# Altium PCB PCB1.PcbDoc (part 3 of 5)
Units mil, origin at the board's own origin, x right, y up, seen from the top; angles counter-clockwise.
Board outline 4463 x 4481 mil, 2 copper layers (Top Layer, Bottom Layer); 0 components, 111 nets, 310 pads, 0 vias.
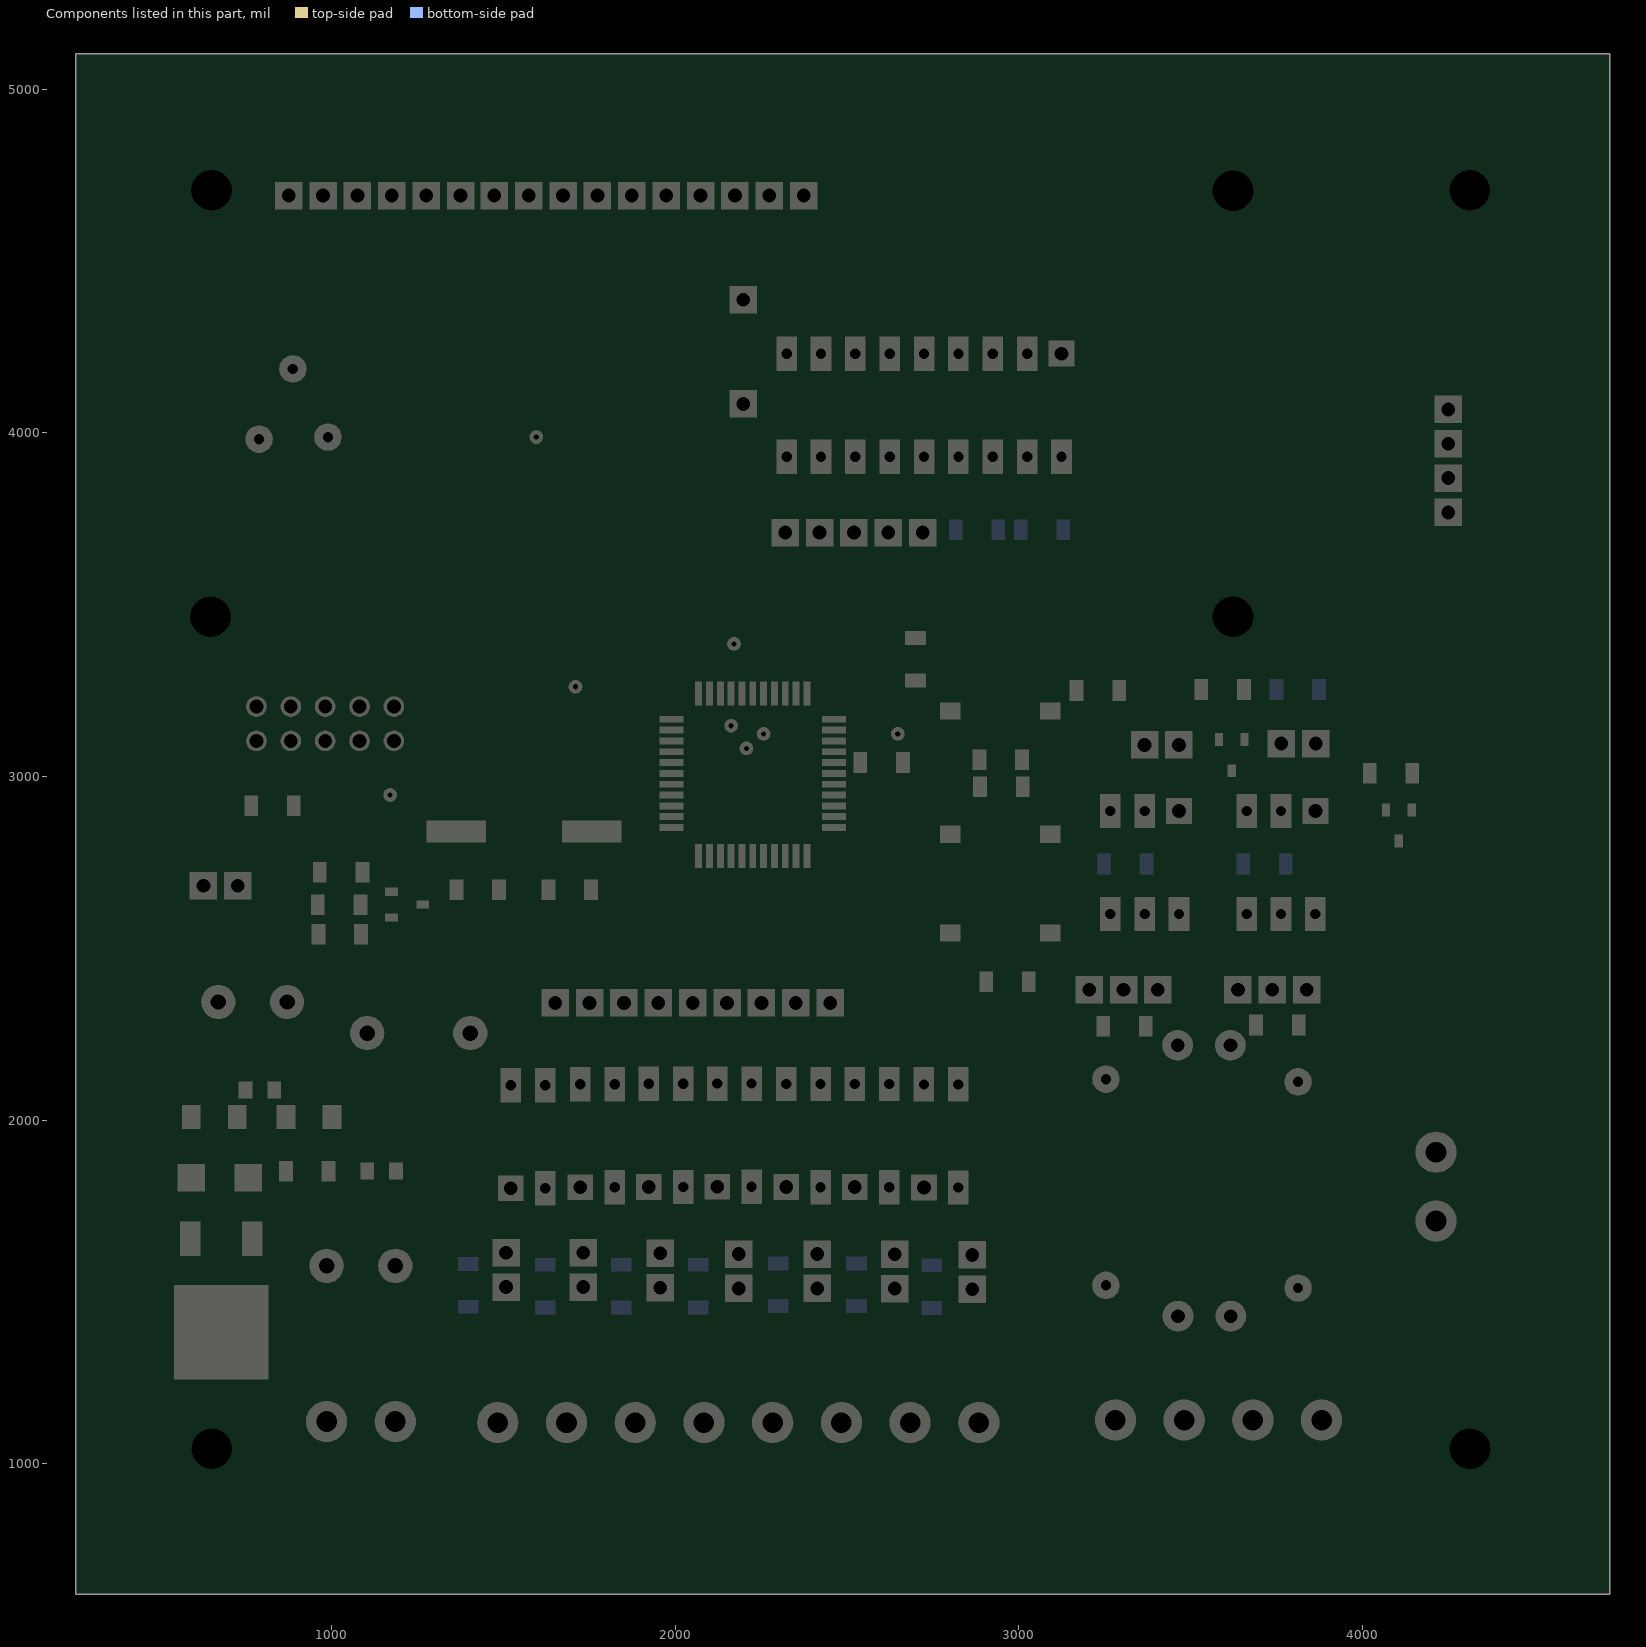
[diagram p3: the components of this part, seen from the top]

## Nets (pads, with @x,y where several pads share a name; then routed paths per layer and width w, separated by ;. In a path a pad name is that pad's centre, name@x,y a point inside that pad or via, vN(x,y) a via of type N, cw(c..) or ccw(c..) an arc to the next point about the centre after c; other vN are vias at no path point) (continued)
copper on no net: (continued)
  Top Layer w15: 3289.04,2179.3 3289.04,2215.2 ; 3289.04,2446.5 3289.04,2522 ; 3289.04,2677 3289.04,2822 ; 3289.04,2976.9 3289.04,3072 ; 3289.04,3694.8 3289.04,4351.8 ; 3289.04,4421.8 3289.04,4841.9 ; 3293.34,2231.9 3322.34,2231.9 ; 3293.34,2256.9 3322.34,2256.9 ; 3293.34,2281.9 3322.34,2281.9 ; 3293.34,2306.9 3322.34,2306.9 ; 3311.44,1556.9 3762.94,1556.9 ; 3311.44,2156.9 3420.54,2156.9 ; 3311.94,1481.9 3413.54,1481.9 ; 3311.94,2081.9 3746.74,2081.9 ; 3314.04,906.9 3314.04,1039.5 ; 3314.04,1214.5 3314.04,1484 ; 3314.04,1554.3 3314.04,2084 ; 3314.04,2154.3 3314.04,2311.5 ; 3314.04,2446.5 3314.04,2522 ; 3314.04,2677 3314.04,2822 ; 3314.04,2976.9 3314.04,3024 ; 3314.04,3719.8 3314.04,4351.8 ; 3314.04,4421.8 3314.04,4841.9 ; 3321.24,1506.9 3745.34,1506.9 ; 3321.24,1531.9 3745.34,1531.9 ; 3321.24,2106.9 3745.34,2106.9 ; 3321.24,2131.9 3745.34,2131.9 ; 3325.14,1206.9 3437.44,1206.9 ; 3334.94,1056.9 3427.64,1056.9 ; 3339.04,906.9 3339.04,1061 ; 3339.04,1193.1 3339.04,2215.2 ; 3339.04,2446.5 3339.04,2522 ; 3339.04,2677 3339.04,2822 ; 3339.04,2999.5 3339.04,3024 ; 3339.04,3744.8 3339.04,4351.8 ; 3339.04,4421.8 3339.04,4841.9 ; 3350.14,1181.9 3412.44,1181.9 ; 3359.94,1081.9 3402.64,1081.9 ; 3364.04,906.9 3364.04,1086 ; 3364.04,1168.1 3364.04,2215.2 ; 3364.04,2446.5 3364.04,2522 ; 3364.04,2677 3364.04,2822 ; 3364.04,3769.8 3364.04,4351.8 ; 3364.04,4421.8 3364.04,4841.9 ; 3368.84,1106.9 3393.84,1106.9 ; 3368.84,1131.9 3393.84,1131.9 ; 3368.84,1156.9 3393.84,1156.9 ; 3389.04,906.9 3389.04,2215.2 ; 3389.04,2446.5 3389.04,2522 ; 3389.04,2677 3389.04,2822 ; 3389.04,3794.8 3389.04,4351.8 ; 3389.04,4421.8 3389.04,4841.9 ; 3414.04,906.9 3414.04,1070.6 ; 3414.04,1183.5 3414.04,1376.6 ; 3414.04,1482.4 3414.04,2163.4 ; 3414.04,2446.5 3414.04,2522 ; 3414.04,2677 3414.04,2822 ; 3414.04,3802.9 3414.04,4351.8 ; 3414.04,4421.8 3414.04,4841.9 ; 3423.84,2831.9 3605.74,2831.9 ; 3439.04,906.9 3439.04,1045.6 ; 3439.04,1208.5 3439.04,1357 ; 3439.04,1502 3439.04,2145.1 ; 3439.04,2290.1 3439.04,2292.4 ; 3439.04,2446.5 3439.04,2522 ; 3439.04,2677 3439.04,2834.5 ; 3439.04,2964.4 3439.04,2981.7 ; 3439.04,3802.9 3439.04,4351.8 ; 3439.04,4421.8 3439.04,4841.9 ; 3440.34,2306.9 3611.04,2306.9 ; 3464.04,906.9 3464.04,1039.5 ; 3464.04,1214.5 3464.04,1357 ; 3464.04,1502 3464.04,2145.1 ; 3464.04,2290.1 3464.04,2311.5 ; 3464.04,2446.5 3464.04,2522 ; 3464.04,2677 3464.04,2834.5 ; 3464.04,2964.4 3464.04,2981.7 ; 3464.04,3802.9 3464.04,4351.8 ; 3464.04,4421.8 3464.04,4841.9 ; 3472.44,2331.9 3570.54,2331.9 ; 3472.44,2356.9 3570.54,2356.9 ; 3472.44,2381.9 3570.54,2381.9 ; 3472.44,2406.9 3570.54,2406.9 ; 3472.44,2431.9 3570.54,2431.9 ; 3489.04,906.9 3489.04,1039.5 ; 3489.04,1214.5 3489.04,1357 ; 3489.04,1502 3489.04,2145.1 ; 3489.04,2290.1 3489.04,2522 ; 3489.04,2677 3489.04,2834.5 ; 3489.04,2964.4 3489.04,2981.7 ; 3489.04,3802.9 3489.04,4351.8 ; 3489.04,4421.8 3489.04,4841.9 ; 3500.64,2281.9 3577.74,2281.9 ; 3504.24,2156.9 3574.04,2156.9 ; 3513.74,1481.9 3567.04,1481.9 ; 3514.04,906.9 3514.04,1039.5 ; 3514.04,1214.5 3514.04,1377.4 ; 3514.04,1481.6 3514.04,2166.7 ; 3514.04,2268.5 3514.04,2522 ; 3514.04,2677 3514.04,2834.5 ; 3514.04,2964.4 3514.04,2981.7 ; 3514.04,3802.9 3514.04,4351.8 ; 3514.04,4421.8 3514.04,4841.9 ; 3518.54,1381.9 3562.14,1381.9 ; 3523.84,2531.9 3605.74,2531.9 ; 3523.84,2556.9 3605.74,2556.9 ; 3523.84,2581.9 3605.74,2581.9 ; 3523.84,2606.9 3605.74,2606.9 ; 3523.84,2631.9 3605.74,2631.9 ; 3523.84,2656.9 3605.74,2656.9 ; 3525.14,1206.9 3637.44,1206.9 ; 3525.64,2256.9 3552.74,2256.9 ; 3529.24,2181.9 3549.04,2181.9 ; 3531.34,2856.9 3605.74,2856.9 ; 3531.34,2881.9 3605.74,2881.9 ; 3531.34,2906.9 3605.74,2906.9 ; 3531.34,2931.9 3605.74,2931.9 ; 3531.34,2956.9 3605.74,2956.9 ; 3534.94,1056.9 3627.64,1056.9 ; 3534.94,2206.9 3543.44,2206.9 ; 3534.94,2231.9 3543.44,2231.9 ; 3536.14,1406.9 3544.64,1406.9 ; 3536.14,1431.9 3544.64,1431.9 ; 3536.14,1456.9 3544.64,1456.9 ; 3539.04,906.9 3539.04,1061 ; 3539.04,1193.1 3539.04,2981.7 ; 3539.04,3802.9 3539.04,4351.8 ; 3539.04,4421.8 3539.04,4666 ; 3539.04,4742.1 3539.04,4841.9 ; 3550.14,1181.9 3612.44,1181.9 ; 3559.94,1081.9 3602.64,1081.9 ; 3564.04,906.9 3564.04,1086 ; 3564.04,1168.1 3564.04,1380.1 ; 3564.04,1478.9 3564.04,2167 ; 3564.04,2268.2 3564.04,2981.7 ; 3564.04,3802.9 3564.04,4351.8 ; 3564.04,4421.8 3564.04,4641 ; 3564.04,4767.1 3564.04,4841.9 ; 3568.84,1106.9 3593.84,1106.9 ; 3568.84,1131.9 3593.84,1131.9 ; 3568.84,1156.9 3593.84,1156.9 ; 3589.04,906.9 3589.04,1357 ; 3589.04,1502 3589.04,2145.1 ; 3589.04,2290.1 3589.04,2311.5 ; 3589.04,2446.5 3589.04,2970.7 ; 3589.04,3802.9 3589.04,4351.8 ; 3589.04,4421.8 3589.04,4617.5 ; 3589.04,4790.6 3589.04,4841.9 ; 3614.04,906.9 3614.04,1070.6 ; 3614.04,1183.5 3614.04,1357 ; 3614.04,1502 3614.04,2145.1 ; 3614.04,2290.1 3614.04,2303.9 ; 3614.04,2446.5 3614.04,2522 ; 3614.04,2677 3614.04,2822 ; 3614.04,3802.9 3614.04,4351.8 ; 3614.04,4421.8 3614.04,4617.5 ; 3614.04,4790.6 3614.04,4841.9 ; 3639.04,906.9 3639.04,1045.6 ; 3639.04,1208.5 3639.04,1357 ; 3639.04,1502 3639.04,2145.1 ; 3639.04,2446.5 3639.04,2522 ; 3639.04,2677 3639.04,2822 ; 3639.04,3802.9 3639.04,4351.8 ; 3639.04,4421.8 3639.04,4617.5 ; 3639.04,4790.6 3639.04,4841.9 ; 3657.74,2156.9 3762.94,2156.9 ; 3664.04,906.9 3664.04,1039.5 ; 3664.04,1214.5 3664.04,1373.8 ; 3664.04,1485.2 3664.04,2163.2 ; 3664.04,2446.5 3664.04,2522 ; 3664.04,2677 3664.04,2822 ; 3664.04,3802.9 3664.04,4344.3 ; 3664.04,4421.8 3664.04,4622.3 ; 3664.04,4785.8 3664.04,4841.9 ; 3667.24,1481.9 3746.74,1481.9 ; 3667.94,4781.9 4267.04,4781.9 ; 3672.14,1381.9 4450.24,1381.9 ; 3673.64,4631.9 4262.94,4631.9 ; 3682.74,2181.9 4450.24,2181.9 ; 3688.44,2206.9 4450.24,2206.9 ; 3689.04,906.9 3689.04,1039.5 ; 3689.04,1214.5 3689.04,1398.8 ; 3689.04,1460.2 3689.04,2219.1 ; 3689.04,2446.5 3689.04,2522 ; 3689.04,2677 3689.04,2822 ; 3689.04,3802.9 3689.04,4319.3 ; 3689.04,4418.3 3689.04,4647.3 ; 3689.04,4760.8 3689.04,4841.9 ; 3689.64,1406.9 4450.24,1406.9 ; 3689.64,1431.9 4450.24,1431.9 ; 3689.64,1456.9 3771.74,1456.9 ; 3692.94,4756.9 4242.04,4756.9 ; 3698.64,4656.9 4237.94,4656.9 ; 3700.44,4406.9 4450.24,4406.9 ; 3709.94,4681.9 4225.84,4681.9 ; 3709.94,4706.9 4225.84,4706.9 ; 3709.94,4731.9 4225.84,4731.9 ; 3714.04,906.9 3714.04,1039.5 ; 3714.04,1214.5 3714.04,2219.1 ; 3714.04,2446.5 3714.04,2522 ; 3714.04,2677 3714.04,2822 ; 3714.04,3802.9 3714.04,4294.3 ; 3714.04,4393.3 3714.04,4841.9 ; 3725.14,1206.9 3837.44,1206.9 ; 3725.44,4381.9 4450.24,4381.9 ; 3734.94,1056.9 3827.64,1056.9 ; 3738.24,2231.9 3767.24,2231.9 ; 3738.24,2256.9 3767.24,2256.9 ; 3738.24,2281.9 3767.24,2281.9 ; 3738.24,2306.9 3767.24,2306.9 ; 3739.04,906.9 3739.04,1061 ; 3739.04,1193.1 3739.04,2311.5 ; 3739.04,2446.5 3739.04,2522 ; 3739.04,2677 3739.04,2807.2 ; 3739.04,3802.9 3739.04,4269.3 ; 3739.04,4368.3 3739.04,4841.9 ; 3750.14,1181.9 3812.44,1181.9 ; 3750.44,4356.9 4450.24,4356.9 ; 3759.94,1081.9 3802.64,1081.9 ; 3764.04,906.9 3764.04,1086 ; 3764.04,1168.1 3764.04,1464.6 ; 3764.04,1558 3764.04,2064.6 ; 3764.04,2158 3764.04,2311.5 ; 3764.04,2446.5 3764.04,2522 ; 3764.04,2677 3764.04,2782.2 ; 3764.04,3802.9 3764.04,4244.3 ; 3764.04,4343.3 3764.04,4841.9 ; 3768.84,1106.9 3793.84,1106.9 ; 3768.84,1131.9 3793.84,1131.9 ; 3768.84,1156.9 3793.84,1156.9 ; 3775.44,4331.9 4450.24,4331.9 ; 3789.04,906.9 3789.04,1443.8 ; 3789.04,1578.8 3789.04,2043.8 ; 3789.04,2178.8 3789.04,2219.1 ; 3789.04,2446.5 3789.04,2522 ; 3789.04,2677 3789.04,2777.1 ; 3789.04,3802.9 3789.04,4219.3 ; 3789.04,4318.3 3789.04,4841.9 ; 3800.44,4306.9 4450.24,4306.9 ; 3814.04,906.9 3814.04,1070.6 ; 3814.04,1183.5 3814.04,1443.8 ; 3814.04,1578.8 3814.04,2043.8 ; 3814.04,2178.8 3814.04,2219.1 ; 3814.04,2446.5 3814.04,2522 ; 3814.04,2677 3814.04,2777.1 ; 3814.04,3802.9 3814.04,4194.3 ; 3814.04,4293.3 3814.04,4841.9 ; 3825.44,4281.9 4450.24,4281.9 ; 3839.04,906.9 3839.04,1045.6 ; 3839.04,1208.5 3839.04,1443.8 ; 3839.04,1578.8 3839.04,2043.8 ; 3839.04,2178.8 3839.04,2219.1 ; 3839.04,2446.5 3839.04,2522 ; 3839.04,2677 3839.04,2777.1 ; 3839.04,3802.9 3839.04,4169.3 ; 3839.04,4268.3 3839.04,4841.9 ; 3850.44,4256.9 4450.24,4256.9 ; 3853.84,1456.9 4450.24,1456.9 ; 3853.84,2056.9 4450.24,2056.9 ; 3862.24,2231.9 4450.24,2231.9 ; 3862.24,2256.9 4450.24,2256.9 ; 3862.64,1556.9 4450.24,1556.9 ; 3862.64,2156.9 4450.24,2156.9 ; 3864.04,906.9 3864.04,1039.5 ; 3864.04,1214.5 3864.04,1467.1 ; 3864.04,1555.5 3864.04,2067.1 ; 3864.04,2155.5 3864.04,2276.4 ; 3864.04,2446.5 3864.04,2522 ; 3864.04,2677 3864.04,2777.1 ; 3864.04,3802.9 3864.04,4144.3 ; 3864.04,4243.3 3864.04,4841.9 ; 3869.54,2281.9 4450.24,2281.9 ; 3873.04,2306.9 4450.24,2306.9 ; 3875.44,4231.9 4450.24,4231.9 ; 3878.84,1481.9 4450.24,1481.9 ; 3878.84,2081.9 4450.24,2081.9 ; 3880.34,1506.9 4450.24,1506.9 ; 3880.34,1531.9 4450.24,1531.9 ; 3880.34,2106.9 4450.24,2106.9 ; 3880.34,2131.9 4450.24,2131.9 ; 3889.04,906.9 3889.04,1039.5 ; 3889.04,1214.5 3889.04,2311.5 ; 3889.04,2446.5 3889.04,2522 ; 3889.04,2677 3889.04,2777.1 ; 3889.04,3802.9 3889.04,4119.3 ; 3889.04,4218.3 3889.04,4841.9 ; 3900.44,4206.9 4450.24,4206.9 ; 3905.54,2331.9 4450.24,2331.9 ; 3905.54,2356.9 4450.24,2356.9 ; 3905.54,2381.9 4450.24,2381.9 ; 3905.54,2406.9 4450.24,2406.9 ; 3905.54,2431.9 4450.24,2431.9 ; 3914.04,906.9 3914.04,1039.5 ; 3914.04,1214.5 3914.04,2522 ; 3914.04,2677 3914.04,2777.1 ; 3914.04,3802.9 3914.04,4094.3 ; 3914.04,4193.3 3914.04,4841.9 ; 3920.74,2531.9 4450.24,2531.9 ; 3920.74,2556.9 4450.24,2556.9 ; 3920.74,2581.9 4450.24,2581.9 ; 3920.74,2606.9 4450.24,2606.9 ; 3920.74,2631.9 4450.24,2631.9 ; 3920.74,2656.9 4450.24,2656.9 ; 3925.14,1206.9 4450.24,1206.9 ; 3925.44,4181.9 4450.24,4181.9 ; 3934.94,1056.9 4226.64,1056.9 ; 3939.04,906.9 3939.04,1061 ; 3939.04,1193.1 3939.04,2777.1 ; 3939.04,3802.9 3939.04,4069.3 ; 3939.04,4168.3 3939.04,4841.9 ; 3950.14,1181.9 4450.24,1181.9 ; 3950.44,4156.9 4450.24,4156.9 ; 3959.94,1081.9 4229.14,1081.9 ; 3964.04,906.9 3964.04,1086 ; 3964.04,1168.1 3964.04,2777.1 ; 3964.04,3802.9 3964.04,4044.3 ; 3964.04,4143.3 3964.04,4841.9 ; 3968.84,1106.9 4254.14,1106.9 ; 3968.84,1131.9 4450.24,1131.9 ; 3968.84,1156.9 4450.24,1156.9 ; 3975.44,4131.9 4182.34,4131.9 ; 3989.04,906.9 3989.04,2777.1 ; 3989.04,3802.9 3989.04,4019.3 ; 3989.04,4118.3 3989.04,4841.9 ; 4000.44,4106.9 4182.34,4106.9 ; 4014.04,906.9 4014.04,2777.1 ; 4014.04,3802.9 4014.04,3994.3 ; 4014.04,4093.3 4014.04,4841.9 ; 4025.44,4081.9 4182.34,4081.9 ; 4039.04,906.9 4039.04,2777.1 ; 4039.04,4068.3 4039.04,4841.9 ; 4050.44,4056.9 4182.34,4056.9 ; 4064.04,906.9 4064.04,2777.1 ; 4064.04,4043.3 4064.04,4841.9 ; 4075.44,4031.9 4182.34,4031.9 ; 4089.04,906.9 4089.04,2766.1 ; 4089.04,4018.3 4089.04,4841.9 ; 4100.44,4006.9 4182.34,4006.9 ; 4103.74,3081.9 4450.24,3081.9 ; 4103.74,3106.9 4450.24,3106.9 ; 4103.74,3131.9 4450.24,3131.9 ; 4103.74,3156.9 4450.24,3156.9 ; 4103.74,3181.9 4450.24,3181.9 ; 4103.74,3206.9 4450.24,3206.9 ; 4103.74,3231.9 4450.24,3231.9 ; 4103.74,3256.9 4450.24,3256.9 ; 4103.74,3281.9 4450.24,3281.9 ; 4103.74,3306.9 4450.24,3306.9 ; 4103.74,3331.9 4450.24,3331.9 ; 4103.74,3356.9 4450.24,3356.9 ; 4103.74,3381.9 4450.24,3381.9 ; 4103.74,3406.9 4450.24,3406.9 ; 4103.74,3431.9 4450.24,3431.9 ; 4103.74,3456.9 4450.24,3456.9 ; 4103.74,3481.9 4450.24,3481.9 ; 4103.74,3506.9 4450.24,3506.9 ; 4103.74,3531.9 4450.24,3531.9 ; 4103.74,3556.9 4450.24,3556.9 ; 4103.74,3581.9 4450.24,3581.9 ; 4103.74,3606.9 4450.24,3606.9 ; 4103.74,3631.9 4450.24,3631.9 ; 4103.74,3656.9 4450.24,3656.9 ; 4103.74,3681.9 4450.24,3681.9 ; 4103.74,3706.9 4182.34,3706.9 ; 4103.74,3731.9 4182.34,3731.9 ; 4103.74,3806.9 4182.34,3806.9 ; 4103.74,3831.9 4182.34,3831.9 ; 4103.74,3856.9 4182.34,3856.9 ; 4103.74,3881.9 4182.34,3881.9 ; 4103.74,3906.9 4182.34,3906.9 ; 4103.74,3931.9 4182.34,3931.9 ; 4103.74,3956.9 4182.34,3956.9 ; 4103.74,3981.9 4182.34,3981.9 ; 4114.04,906.9 4114.04,2766.1 ; 4114.04,3066.3 4114.04,3732.9 ; 4114.04,3802.9 4114.04,4841.9 ; 4139.04,906.9 4139.04,1658.1 ; 4139.04,1755 4139.04,1858.1 ; 4139.04,1955 4139.04,2766.1 ; 4139.04,3066.3 4139.04,3732.9 ; 4139.04,3802.9 4139.04,4841.9 ; 4145.64,2781.9 4450.24,2781.9 ; 4145.64,2806.9 4450.24,2806.9 ; 4145.64,2831.9 4450.24,2831.9 ; 4164.04,906.9 4164.04,1633.1 ; 4164.04,1780 4164.04,1833.1 ; 4164.04,1980 4164.04,2856.6 ; 4164.04,3066.3 4164.04,3732.9 ; 4164.04,3802.9 4164.04,4841.9 ; 4183.04,2856.9 4450.24,2856.9 ; 4183.04,2881.9 4450.24,2881.9 ; 4183.04,2906.9 4450.24,2906.9 ; 4183.04,2931.9 4450.24,2931.9 ; 4189.04,906.9 4189.04,1619 ; 4189.04,1794 4189.04,1819 ; 4189.04,1994 4189.04,2951.3 ; 4189.04,3066.3 4189.04,3700.4 ; 4189.04,4135.4 4189.04,4841.9 ; 4192.94,2956.9 4450.24,2956.9 ; 4192.94,2981.9 4450.24,2981.9 ; 4192.94,3006.9 4450.24,3006.9 ; 4192.94,3031.9 4450.24,3031.9 ; 4192.94,3056.9 4450.24,3056.9 ; 4214.04,906.9 4214.04,1619 ; 4214.04,1794 4214.04,1819 ; 4214.04,1994 4214.04,3700.4 ; 4214.04,4135.4 4214.04,4841.9 ; 4239.04,906.9 4239.04,995.3 ; 4239.04,1091.8 4239.04,1619 ; 4239.04,1794 4239.04,1819 ; 4239.04,1994 4239.04,3700.4 ; 4239.04,4135.4 4239.04,4655.8 ; 4239.04,4753.9 4239.04,4841.9 ; 4262.74,1781.9 4450.24,1781.9 ; 4262.74,1981.9 4450.24,1981.9 ; 4263.44,1631.9 4450.24,1631.9 ; 4263.44,1831.9 4450.24,1831.9 ; 4264.04,906.9 4264.04,970.3 ; 4264.04,1116.8 4264.04,1632.5 ; 4264.04,1780.6 4264.04,1832.5 ; 4264.04,1980.6 4264.04,3700.4 ; 4264.04,4135.4 4264.04,4630.8 ; 4264.04,4778.9 4264.04,4841.9 ; 4287.74,1756.9 4450.24,1756.9 ; 4287.74,1956.9 4450.24,1956.9 ; 4288.44,1656.9 4450.24,1656.9 ; 4288.44,1856.9 4450.24,1856.9 ; 4289.04,906.9 4289.04,957 ; 4289.04,1130.1 4289.04,1657.5 ; 4289.04,1755.6 4289.04,1857.5 ; 4289.04,1955.6 4289.04,3700.4 ; 4289.04,4135.4 4289.04,4618.3 ; 4289.04,4791.4 4289.04,4841.9 ; 4301.84,1681.9 4450.24,1681.9 ; 4301.84,1706.9 4450.24,1706.9 ; 4301.84,1731.9 4450.24,1731.9 ; 4301.84,1881.9 4450.24,1881.9 ; 4301.84,1906.9 4450.24,1906.9 ; 4301.84,1931.9 4450.24,1931.9 ; 4314.04,906.9 4314.04,957 ; 4314.04,1130.1 4314.04,3700.4 ; 4314.04,4135.4 4314.04,4618.3 ; 4314.04,4791.4 4314.04,4841.9 ; 4317.34,3706.9 4450.24,3706.9 ; 4317.34,3731.9 4450.24,3731.9 ; 4317.34,3756.9 4450.24,3756.9 ; 4317.34,3781.9 4450.24,3781.9 ; 4317.34,3806.9 4450.24,3806.9 ; 4317.34,3831.9 4450.24,3831.9 ; 4317.34,3856.9 4450.24,3856.9 ; 4317.34,3881.9 4450.24,3881.9 ; 4317.34,3906.9 4450.24,3906.9 ; 4317.34,3931.9 4450.24,3931.9 ; 4317.34,3956.9 4450.24,3956.9 ; 4317.34,3981.9 4450.24,3981.9 ; 4317.34,4006.9 4450.24,4006.9 ; 4317.34,4031.9 4450.24,4031.9 ; 4317.34,4056.9 4450.24,4056.9 ; 4317.34,4081.9 4450.24,4081.9 ; 4317.34,4106.9 4450.24,4106.9 ; 4317.34,4131.9 4450.24,4131.9 ; 4339.04,906.9 4339.04,957 ; 4339.04,1130.1 4339.04,4618.3 ; 4339.04,4791.4 4339.04,4841.9 ; 4357.74,4781.9 4450.24,4781.9 ; 4361.84,4631.9 4450.24,4631.9 ; 4364.04,906.9 4364.04,972 ; 4364.04,1115.1 4364.04,4634.1 ; 4364.04,4775.6 4364.04,4841.9 ; 4372.24,1106.9 4450.24,1106.9 ; 4373.94,981.9 4450.24,981.9 ; 4382.74,4756.9 4450.24,4756.9 ; 4386.84,4656.9 4450.24,4656.9 ; 4389.04,906.9 4389.04,997 ; 4389.04,1090.1 4389.04,4659.1 ; 4389.04,4750.6 4389.04,4841.9 ; 4397.24,1081.9 4450.24,1081.9 ; 4398.94,1006.9 4450.24,1006.9 ; 4398.94,4681.9 4450.24,4681.9 ; 4398.94,4706.9 4450.24,4706.9 ; 4398.94,4731.9 4450.24,4731.9 ; 4399.74,1031.9 4450.24,1031.9 ; 4399.74,1056.9 4450.24,1056.9 ; 4414.04,906.9 4414.04,4841.9 ; 4439.04,906.9 4439.04,4841.9 ; 514.04,906.9 514.04,4841.9 ; 514.04,906.9 4450.24,906.9 ; 514.04,906.9 4450.24,906.9 ; 514.04,906.9 514.04,4841.9 ; 514.04,4841.9 4450.24,4841.9 ; 514.04,4841.9 4450.24,4841.9 ; 639.04,2266.1 593.64,2311.5 593.64,2375.7 639.04,2421.1 ; 639.04,2266.1 703.24,2266.1 709.94,2272.7 709.94,2140.1 702.44,2140.1 702.44,2130.1 594.54,2130.1 549.94,2085.6 549.94,2071.4 537.44,2071.4 537.44,1946.4 549.94,1946.4 549.94,1899.2 524.94,1899.2 524.94,1764.2 547.14,1764.2 547.14,1732.1 532.14,1732.1 532.14,1577.1 647.14,1577.1 647.14,1732.1 632.14,1732.1 632.14,1764.2 659.94,1764.2 659.94,1899.2 634.94,1899.2 634.94,1946.4 647.44,1946.4 647.44,2045.1 671.24,2045.1 671.24,1946.4 781.24,1946.4 781.24,1966.4 813.04,1966.4 813.04,1946.4 825.54,1946.4 825.54,1908.9 820.54,1908.9 820.54,1899.2 690.94,1899.2 690.94,1764.2 715.24,1764.2 715.24,1732.1 712.14,1732.1 712.14,1577.1 827.14,1577.1 827.14,1614.6 915.24,1614.6 908.64,1607.9 908.64,1543.7 954.04,1498.3 1018.24,1498.3 1063.64,1543.7 1063.64,1607.9 1026.14,1645.4 1026.14,1716.6 1032.04,1722.5 1032.04,1793.9 1039.54,1793.9 1039.54,1808.9 1056.74,1808.9 1056.74,1798.9 1148.24,1798.9 1148.24,1647.5 1108.64,1607.9 1108.64,1543.7 1138.64,1513.7 1138.64,1510.7 1057.94,1430.1 844.64,1430.1 844.64,1547.6 514.64,1547.6 514.64,1217.6 844.64,1217.6 844.64,1335.1 1097.34,1335.1 1233.64,1471.4 1233.64,1513.7 1263.64,1543.7 1263.64,1607.9 1228.24,1643.3 1228.24,1798.9 1235.74,1798.9 1235.74,1811.4 1263.74,1811.4 1277.44,1825.2 1277.44,1266.5 1396.64,1147.3 1396.64,1083.7 1447.94,1032.4 1520.44,1032.4 1571.64,1083.7 1571.64,1156.2 1520.44,1207.4 1456.74,1207.4 1362.44,1301.7 1362.44,2185.2 1372.14,2175.5 1436.34,2175.5 1481.74,2220.9 1481.74,2285.1 1436.34,2330.5 1372.14,2330.5 1337.14,2295.5 1334.64,2295.5 1287.14,2248 1287.14,2344.3 1356.84,2414 1356.84,2540.8 1502.54,2540.8 1523.04,2561.3 1523.04,2612.8 1535.54,2612.8 1535.54,2635.3 1584.34,2635.3 1584.34,2612.8 1679.34,2612.8 1679.34,2727.8 1584.34,2727.8 1584.34,2705.3 1535.54,2705.3 1535.54,2727.8 1440.54,2727.8 1440.54,2612.8 1453.04,2612.8 1453.04,2610.8 1362.84,2610.8 1360.84,2612.8 1411.54,2612.8 1411.54,2727.8 1399.04,2727.8 1399.04,2780.6 1478.04,2780.6 1478.04,2804.6 1540.04,2804.6 1677.74,2942.3 1759.94,2942.3 1722.74,2905.2 1722.74,2898.5 1643.74,2898.5 1643.74,2780.6 1720.84,2780.6 1720.84,2727.8 1708.34,2727.8 1708.34,2612.8 1748.84,2612.8 1714.14,2578.1 1714.14,2408.3 1583.94,2408.3 1583.94,2273.3 2518.84,2273.3 2518.84,2408.3 2486.34,2408.3 2486.34,2473.8 2259.34,2701 2259.34,2706.3 2421.24,2706.3 2421.24,2813.9 2524.94,2813.9 2524.94,2847.9 2692.04,2847.9 2695.14,2844.8 2695.14,2549.5 2735.34,2509.3 2743.44,2509.3 2743.44,2491.8 2858.44,2491.8 2858.44,2509.3 2866.84,2509.3 2872.24,2503.9 2872.24,2460.1 2857.84,2460.1 2857.84,2345.1 2952.84,2345.1 2952.84,2460.1 2942.24,2460.1 2942.24,2532.9 2895.84,2579.3 2858.44,2579.3 2858.44,2596.8 2765.14,2596.8 2765.14,2779.2 2858.44,2779.2 2858.44,2796.7 2878.44,2796.7 2922.64,2840.9 2922.64,2911.9 2935.14,2911.9 2935.14,3026.9 2933.14,3026.9 2933.14,3105.7 2920.64,3105.7 2920.64,3180.8 2874.54,3226.9 2858.44,3226.9 2858.44,3239.6 3034.84,3239.6 3034.84,3137.4 3057.34,3137.4 3057.34,3026.9 3057.14,3026.9 3057.14,3105.7 2962.14,3105.7 2962.14,2990.7 2964.14,2990.7 2964.14,2911.9 2976.64,2911.9 2976.64,2874.3 2994.34,2856.6 2994.34,2460.1 2981.84,2460.1 2981.84,2345.1 2994.34,2345.1 2994.34,2166.3 2966.84,2138.8 2881.74,2138.8 2881.74,2181.3 2680.54,2181.3 2680.54,2182.5 2280.24,2182.5 2280.24,2183.7 2065.24,2183.7 2065.24,2182.9 1866.04,2182.9 1866.04,2182.1 1666.84,2182.1 1666.84,2178.9 1464.84,2178.9 1464.84,2023.9 1679.84,2023.9 1679.84,2027.1 1881.84,2027.1 1881.84,2027.9 2081.04,2027.9 2081.04,2028.7 2266.04,2028.7 2266.04,2027.5 2666.74,2027.5 2666.74,2026.3 2881.74,2026.3 2881.74,2068.8 2995.84,2068.8 3064.34,2137.3 3064.34,2345.1 3076.84,2345.1 3076.84,2400.6 3091.04,2414.9 3134.34,2414.9 3137.44,2417.9 3137.44,2311.5 3169.94,2311.5 3169.94,2299.1 3198.34,2270.7 3198.34,2215.2 3293.34,2215.2 3293.34,2311.5 3322.34,2311.5 3322.34,2215.2 3389.94,2215.2 3389.94,2187.5 3432.34,2145.1 3492.44,2145.1 3534.94,2187.5 3534.94,2247.6 3492.44,2290.1 3436.74,2290.1 3440.34,2293.6 3440.34,2311.5 3472.44,2311.5 3472.44,2446.5 3166.04,2446.5 3194.24,2474.7 3194.24,3124.2 3255.44,3185.5 3255.44,3192.6 3257.34,3192.6 3257.34,3103.8 3298.84,3062.2 3298.84,3024 3363.54,3024 3331.34,2991.8 3331.34,2976.9 3208.84,2976.9 3208.84,2822 3423.84,2822 3423.84,2834.5 3531.34,2834.5 3531.34,2964.4 3423.84,2964.4 3423.84,2976.9 3415.34,2976.9 3420.24,2981.7 3580.34,2981.7 3580.34,2970.7 3605.74,2970.7 3605.74,2822 3728.24,2822 3728.24,2818 3769.14,2777.1 4066.64,2777.1 4066.64,2766.1 4145.64,2766.1 4145.64,2856.6 4183.04,2856.6 4183.04,2948.5 4178.54,2948.5 4178.54,2951.3 4192.94,2951.3 4192.94,3066.3 4103.74,3066.3 4103.74,3732.9 4182.34,3732.9 4182.34,3700.4 4317.34,3700.4 4317.34,4135.4 4182.34,4135.4 4182.34,3802.9 4103.74,3802.9 4103.74,4003.6 3685.54,4421.8 2266.24,4421.8 2266.24,4454.3 2131.24,4454.3 2131.24,4319.3 2266.24,4319.3 2266.24,4351.8 3656.54,4351.8 4033.74,3974.6 4033.74,3802.9 3397.14,3802.9 3216.44,3622.2 2755.64,3622.2 2755.64,3642.1 2788.14,3642.1 2788.14,3777.1 2253.24,3777.1 2253.24,3642.1 2284.84,3642.1 2268.84,3626 2233.74,3661.1 2233.74,4016.1 2266.24,4016.1 2266.24,4151.1 2131.24,4151.1 2131.24,4016.1 2163.74,4016.1 2163.74,3632.1 2222.74,3573.1 2222.74,3383.9 2219.04,3387.6 2219.04,3405.3 2191.24,3433.1 2151.84,3433.1 2127.44,3408.6 2127.44,4486.4 2210.14,4569.1 2210.14,4622.4 2441.84,4622.4 2441.84,4757.4 1410.94,4757.4 1410.94,4764.6 1390.34,4785.1 1377.44,4798.1 810.64,4798.1 765.74,4753.2 765.74,4506.5 1056.24,4216 1056.24,4016.4 1018.04,4054.7 962.14,4054.7 922.54,4015.1 922.54,3959.2 962.14,3919.7 1018.04,3919.7 1056.24,3957.9 1056.24,3571.3 824.64,3339.8 824.64,3920.8 857.14,3953.3 857.14,4009.2 817.64,4048.7 761.74,4048.7 722.14,4009.2 722.14,3953.3 754.64,3920.8 754.64,3336.3 665.34,3246.9 665.34,3015.6 692.54,2988.4 931.44,2988.4 931.44,2972.6 843.34,2972.6 843.34,2857.7 931.44,2857.7 931.44,2779 918.94,2779 918.94,2756.5 916.54,2756.5 872.34,2712.4 872.34,2545.6 912.54,2505.4 915.04,2505.4 915.04,2482.9 930.64,2482.9 930.64,2393.7 903.24,2421.1 839.04,2421.1 ; 639.04,2421.1 703.24,2421.1 748.64,2375.7 748.64,2374.6 789.94,2333.4 789.94,2140.1 793.94,2140.1 793.94,2220.8 839.24,2266.1 839.04,2266.1 ; 839.04,2266.1 793.64,2311.5 793.64,2375.7 839.04,2421.1 ; 4450.24,906.9 4450.24,4841.9 ; 4450.24,906.9 4450.24,4841.9 ; 560.34,2614.6 560.34,2749.6 692.84,2749.6 692.84,2841.9 719.34,2868.4 719.34,2972.6 814.34,2972.6 814.34,2857.7 801.84,2857.7 801.84,2851.9 762.84,2812.9 762.84,2749.6 795.34,2749.6 795.34,2614.6 560.34,2614.6 ; 561.74,3428.5 612.44,3377.8 684.14,3377.8 734.84,3428.5 734.84,3500.2 684.14,3550.9 612.44,3550.9 561.74,3500.2 561.74,3428.5 ; 564.94,4669.8 615.64,4619.1 687.34,4619.1 738.04,4669.8 738.04,4741.5 687.34,4792.2 615.64,4792.2 564.94,4741.5 564.94,4669.8 ; 565.74,1007.7 616.44,957 688.14,957 738.84,1007.7 738.84,1079.4 688.14,1130.1 616.44,1130.1 565.74,1079.4 565.74,1007.7 ; 820.64,4157.6 820.64,4213.5 860.14,4253.1 916.04,4253.1 955.64,4213.5 955.64,4157.6 916.04,4118.1 860.14,4118.1 820.64,4157.6 ; 898.64,1086.8 949.84,1035.6 1022.34,1035.6 1073.64,1086.8 1073.64,1159.3 1022.34,1210.6 949.84,1210.6 898.64,1159.3 898.64,1086.8 ; 1098.64,1086.8 1149.84,1035.6 1222.34,1035.6 1273.64,1086.8 1273.64,1159.3 1222.34,1210.6 1149.84,1210.6 1098.64,1159.3 1098.64,1086.8 ; 1441.04,1446.5 1441.04,1681.5 1576.04,1681.5 1576.04,1546.5 1576.04,1446.5 1441.04,1446.5 ; 1457.34,1736.4 1457.34,1866.4 1564.84,1866.4 1564.84,1878.9 1679.84,1878.9 1679.84,1869.6 1766.84,1869.6 1766.84,1882.1 1881.84,1882.1 1881.84,1870.4 1966.04,1870.4 1966.04,1882.9 2081.04,1882.9 2081.04,1871.2 2165.24,1871.2 2165.24,1883.7 2280.24,1883.7 2280.24,1870 2366.04,1870 2366.04,1882.5 2481.04,1882.5 2481.04,1870 2565.54,1870 2565.54,1882.5 2680.54,1882.5 2680.54,1868.8 2766.74,1868.8 2766.74,1881.3 2881.74,1881.3 2881.74,1726.3 2766.74,1726.3 2766.74,1738.8 2680.54,1738.8 2680.54,1727.5 2565.54,1727.5 2565.54,1740 2481.04,1740 2481.04,1727.5 2366.04,1727.5 2366.04,1740 2280.24,1740 2280.24,1728.7 2165.24,1728.7 2165.24,1741.2 2081.04,1741.2 2081.04,1727.9 1966.04,1727.9 1966.04,1740.4 1881.84,1740.4 1881.84,1727.1 1766.84,1727.1 1766.84,1739.6 1679.84,1739.6 1679.84,1723.9 1564.84,1723.9 1564.84,1736.4 1457.34,1736.4 ; 1596.64,1083.7 1647.94,1032.4 1720.44,1032.4 1771.64,1083.7 1771.64,1156.2 1720.44,1207.4 1647.94,1207.4 1596.64,1156.2 1596.64,1083.7 ; 1665.44,1446.5 1665.44,1681.5 1800.44,1681.5 1800.44,1546.5 1800.44,1446.5 1665.44,1446.5 ; 1796.64,1083.7 1847.94,1032.4 1920.44,1032.4 1971.64,1083.7 1971.64,1156.2 1920.44,1207.4 1847.94,1207.4 1796.64,1156.2 1796.64,1083.7 ; 1889.84,1445 1889.84,1680 2024.84,1680 2024.84,1545 2024.84,1445 1889.84,1445 ; 1996.64,1083.7 2047.94,1032.4 2120.44,1032.4 2171.64,1083.7 2171.64,1156.2 2120.44,1207.4 2047.94,1207.4 1996.64,1156.2 1996.64,1083.7 ; 2118.24,1442.6 2118.24,1677.6 2253.24,1677.6 2253.24,1542.6 2253.24,1442.6 2118.24,1442.6 ; 2196.64,1083.7 2247.94,1032.4 2320.44,1032.4 2371.64,1083.7 2371.64,1156.2 2320.44,1207.4 2247.94,1207.4 2196.64,1156.2 2196.64,1083.7 ; 2267.24,3852.6 2267.24,4007.6 3182.14,4007.6 3182.14,3852.6 2267.24,3852.6 ; 2267.24,4152.6 2267.24,4307.6 3082.14,4307.6 3082.14,4295.1 3189.64,4295.1 3189.64,4165.1 3082.14,4165.1 3082.14,4152.6 2267.24,4152.6 ; 2346.54,1442.6 2346.54,1677.6 2481.54,1677.6 2481.54,1542.6 2481.54,1442.6 2346.54,1442.6 ; 2396.64,1083.7 2447.94,1032.4 2520.34,1032.4 2571.54,1083.7 2571.54,1156.2 2520.34,1207.4 2447.94,1207.4 2396.64,1156.2 2396.64,1083.7 ; 2572.04,1442.2 2572.04,1677.2 2707.04,1677.2 2707.04,1542.2 2707.04,1442.2 2572.04,1442.2 ; 2596.54,1083.7 2647.84,1032.4 2720.34,1032.4 2771.54,1083.7 2771.54,1156.2 2720.34,1207.4 2647.84,1207.4 2596.54,1156.2 2596.54,1083.7 ; 2796.54,1083.7 2847.84,1032.4 2920.34,1032.4 2971.54,1083.7 2971.54,1156.2 2920.34,1207.4 2847.84,1207.4 2796.54,1156.2 2796.54,1083.7 ; 2797.24,1440.2 2797.24,1675.2 2932.24,1675.2 2932.24,1540.2 2932.24,1440.2 2797.24,1440.2 ; 3186.24,1491.2 3186.24,1547.1 3225.74,1586.6 3281.74,1586.6 3321.24,1547.1 3321.24,1491.2 3281.74,1451.6 3225.74,1451.6 3186.24,1491.2 ; 3186.24,2091.2 3186.24,2147.1 3225.74,2186.6 3281.74,2186.6 3321.24,2147.1 3321.24,2091.2 3281.74,2051.6 3225.74,2051.6 3186.24,2091.2 ; 3193.84,1090.8 3193.84,1163.3 3245.04,1214.5 3317.54,1214.5 3368.84,1163.3 3368.84,1090.8 3317.54,1039.5 3245.04,1039.5 3193.84,1090.8 ; 3208.84,2522 3208.84,2677 3523.84,2677 3523.84,2522 3208.84,2522 ; 3391.14,1399.4 3391.14,1459.5 3433.64,1502 3493.64,1502 3536.14,1459.5 3536.14,1399.4 3493.64,1357 3433.64,1357 3391.14,1399.4 ; 3393.84,1090.8 3393.84,1163.3 3445.04,1214.5 3517.54,1214.5 3568.84,1163.3 3568.84,1090.8 3517.54,1039.5 3445.04,1039.5 3393.84,1090.8 ; 3536.84,4668.2 3587.54,4617.5 3659.24,4617.5 3709.94,4668.2 3709.94,4739.9 3659.24,4790.6 3587.54,4790.6 3536.84,4739.9 3536.84,4668.2 ; 3543.44,2187.5 3543.44,2247.6 3585.94,2290.1 3627.84,2290.1 3606.44,2311.5 3570.54,2311.5 3570.54,2446.5 3905.54,2446.5 3905.54,2311.5 3873.04,2311.5 3873.04,2285.4 3862.24,2274.6 3862.24,2219.1 3767.24,2219.1 3767.24,2311.5 3738.24,2311.5 3738.24,2219.1 3688.44,2219.1 3688.44,2187.5 3645.94,2145.1 3585.94,2145.1 3543.44,2187.5 ; 3544.64,1399.4 3544.64,1459.5 3587.14,1502 3647.24,1502 3689.64,1459.5 3689.64,1399.4 3647.24,1357 3587.14,1357 3544.64,1399.4 ; 3593.84,1090.8 3593.84,1163.3 3645.04,1214.5 3717.54,1214.5 3768.84,1163.3 3768.84,1090.8 3717.54,1039.5 3645.04,1039.5 3593.84,1090.8 ; 3605.74,2522 3605.74,2677 3920.74,2677 3920.74,2522 3605.74,2522 ; 3745.34,1483.3 3745.34,1539.2 3784.84,1578.8 3840.74,1578.8 3880.34,1539.2 3880.34,1483.3 3840.74,1443.8 3784.84,1443.8 3745.34,1483.3 ; 3745.34,2083.3 3745.34,2139.2 3784.84,2178.8 3840.74,2178.8 3880.34,2139.2 3880.34,2083.3 3840.74,2043.8 3784.84,2043.8 3745.34,2083.3 ; 3793.84,1090.8 3793.84,1163.3 3845.04,1214.5 3917.54,1214.5 3968.84,1163.3 3968.84,1090.8 3917.54,1039.5 3845.04,1039.5 3793.84,1090.8 ; 4126.84,1670.3 4126.84,1742.8 4178.14,1794 4250.64,1794 4301.84,1742.8 4301.84,1670.3 4250.64,1619 4178.14,1619 4126.84,1670.3 ; 4126.84,1870.3 4126.84,1942.8 4178.14,1994 4250.64,1994 4301.84,1942.8 4301.84,1870.3 4250.64,1819 4178.14,1819 4126.84,1870.3 ; 4225.84,4669 4276.54,4618.3 4348.24,4618.3 4398.94,4669 4398.94,4740.7 4348.24,4791.4 4276.54,4791.4 4225.84,4740.7 4225.84,4669 ; 4226.64,1007.7 4277.34,957 4349.04,957 4399.74,1007.7 4399.74,1079.4 4349.04,1130.1 4277.34,1130.1 4226.64,1079.4 4226.64,1007.7
  Bottom Layer w8: 513.64,906.5 513.64,4843.5 4450.64,4843.5 4450.64,906.5 513.64,906.5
